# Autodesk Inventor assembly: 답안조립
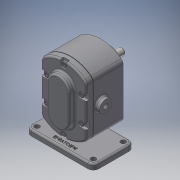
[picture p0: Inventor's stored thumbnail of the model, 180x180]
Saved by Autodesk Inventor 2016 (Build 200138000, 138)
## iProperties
Created: 2019-03
Part Number: 답안조립
Document SubType Name: Assembly
Designer: Administrator
Author: Administrator
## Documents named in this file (11)
- C:\Users\Administrator\Desktop\490308V1005\답안조립.iam
- C:\Users\Administrator\Desktop\490308V1005\본체.ipt
- C:\Users\Administrator\Desktop\490308V1005\메인축.ipt
- C:\Users\Administrator\Desktop\490308V1005\키 6 x 6 x 18.ipt
- C:\Users\Administrator\Desktop\490308V1005\베어링부시.ipt
- C:\Users\Administrator\Desktop\490308V1005\커버.ipt
- C:\Users\Administrator\Desktop\490308V1005\서브축.ipt
- C:\Users\Administrator\Desktop\490308V1005\오일 실 16 28 7.ipt
- C:\Users\Administrator\Desktop\490308V1005\볼트 M5.ipt
- C:\Users\Administrator\Desktop\490308V1005\스퍼기어.ipt
- C:\Users\Administrator\Desktop\490308V1005\개스킷.ipt
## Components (1 placed, 1 different names)
1. 개스킷:1
